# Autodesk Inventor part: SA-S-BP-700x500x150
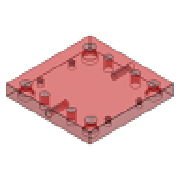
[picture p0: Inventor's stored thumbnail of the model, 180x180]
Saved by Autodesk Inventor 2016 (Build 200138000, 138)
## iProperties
Created: 2015-02
Part Number: SA-S-BP-700x500x150
Material: S 55 C
Description: Core Plate
Document SubType Name: Modeling
Designer: Sandeep
Standard Revision: 1
Manufacturer: FUTABA
Language: en-US
Size Designation: 700x500x150
Categories: <MemberInstance><Categories><Category DisplayName="Mold" InternalName="349578f2-f4d4-4954-8c09-8e99297a61c0" Mnemonic="MOLD"><Category DisplayName="Mold Plates"
Density: 7.85 g/cm^3
Appearance: Dark Red
IsCustomPart: 1
Author: Sandeep
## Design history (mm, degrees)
sketch "Sketch1"
  geometry: L1 (-250, 350)-(250, 350); L2 (250, 350)-(250, -350); L3 (250, -350)-(-250, -350); L4 (-250, -350)-(-250, 350); 7 further points
  constraints: 8 end point, 2 horizontal alignment, 2 midpoint, 2 parallel, 1 horizontal, 1 perpendicular, 1 vertical alignment
  dimensions: "d123" = 500 distance between parallel lines of L2 L4 (= W_); "d124" = 700 distance between parallel lines of L3 L1 (= L); "d125" = 317 vertical distance of point (0, 0) point (-128, 317) (= 0.5 x RP_L); "d126" = 128 horizontal distance of point (0, 0) point (-128, 317) (= 0.5 x RP_W); "d127" = 207 horizontal distance of point (0, 0) point (-207, 307) (= 0.5 x GP_W); "d128" = 307 vertical distance of point (0, 0) point (-207, 307) (= 0.5 x GP_L); "d129" = 205 horizontal distance of point (0, 0) point (-205, 243) (= 0.5 x S1_W); "d130" = 243 vertical distance of point (0, 0) point (-205, 243) (= 0.5 x S1_L); "d140" = 207 horizontal distance of point (207, 307) point (0, 0) (= 0.5 x GP_W)
extrude "Extrusion1" new body sketch "Sketch1" distance "d20" = 150 (= H_); taper "d30" = 0 deg
body "Solid1"
sketch "Sketch2"
  geometry: L1 (500, 0)-(0, 0) reference; 3 further points
  constraints: 1 midpoint, 1 vertical alignment
  dimensions: "d186" = 75 distance from line of L1 point (250, 75) (= 0.5 x H_)
hole "Hole1" sketch "Sketch2" diameter "d104" = 31.67; stored, may be unused: countersink angle "d108" = 90 deg, drill point angle "d110" = 118 deg; dims "d105" = 59 (= le), "d106" = 46 (= GP_d2), "d107" = 10 (= GP_k), "d109" = 82 (= ke)
sketch "Sketch3"
  geometry: L1 (0, 0)-(500, 0) reference; 3 further points
  constraints: 1 midpoint, 1 vertical alignment
  dimensions: "d187" = 75 distance from line of point (250, -75) L1 (= 0.5 x H_)
hole "Hole2" sketch "Sketch3" diameter "d113" = 31.67; stored, may be unused: countersink angle "d117" = 90 deg, drill point angle "d119" = 118 deg; dims "d114" = 59 (= le), "d115" = 46 (= GP_d2), "d116" = 10 (= GP_k), "d118" = 82 (= ke)
hole "Hole3" sketch "Sketch1" diameter "d131" = 13.835; stored, may be unused: countersink angle "d135" = 90 deg, drill point angle "d137" = 118 deg; dims "d132" = 20 (= H_l), "d133" = 4, "d134" = 2, "d136" = 30 (= H_u)
pattern_linear "Rectangular Pattern1" dims "d164" = 243 (computed from S1_L, Ns)
hole "Hole4" sketch "Sketch1" diameter "d141" = 40 (= GP_d1); stored, may be unused: countersink angle "d145" = 90 deg, drill point angle "d147" = 0 deg; dims "d142" = 6, "d143" = 46 (= GP_d2), "d144" = 10 (= GP_k), "d146" = 150 (= H_)
pattern_linear "Rectangular Pattern2" dims "d170" = 614 (computed from GP_L, Nl)
hole "Hole5" sketch "Sketch1" diameter "d148" = 40 (= GP_d1); stored, may be unused: countersink angle "d152" = 90 deg, drill point angle "d154" = 0 deg; dims "d149" = 6, "d150" = 46 (= GP_d2), "d151" = 10 (= GP_k), "d153" = 150 (= H_)
pattern_linear "Rectangular Pattern3" dims "d173" = 612 (computed from GP_L2, GP_L1, Nl)
hole "Hole6" sketch "Sketch1" diameter "d155" = 30 (= RP_dt); stored, may be unused: countersink angle "d159" = 90 deg, drill point angle "d161" = 0 deg; dims "d156" = 6, "d157" = 46 (= GP_d2), "d158" = 10 (= GP_k), "d160" = 150 (= H_)
pattern_linear "Rectangular Pattern4" dims "d176" = 634 (computed from RP_L, Nl), "d179" = 256 (computed from RP_W, Nw)
chamfer "Chamfer1" distance "d180" = 0.5; stored, may be unused: second distance "d181" = 2, angle "d182" = 45 deg
other parameters: "L" = 700 [user parameter; used in 1 equation term], "W_" = 500 [user parameter; used in 3 equation terms], "H_" = 150 [user parameter; used in 8 equation terms], "GP_W" = 414 [user parameter; used in 2 equation terms], "GP_d1" = 40 [user parameter; used in 2 equation terms], "GP_d2" = 46 [user parameter; used in 5 equation terms], "GP_k" = 10 [user parameter; used in 5 equation terms], "S1_L" = 486 [user parameter; used in 2 equation terms], "GP_L1" = 307 [user parameter; used in 1 equation term], "GP_L2" = 305 [user parameter; used in 1 equation term], "RP_L" = 634 [user parameter; used in 2 equation terms], "RP_W" = 256 [user parameter; used in 2 equation terms], "RP_dt" = 30 [user parameter; used in 1 equation term], "GP_L" = 614 [user parameter; used in 2 equation terms], "d102" = 75 (= 0.5 x H_), "d112" = 75 (= 0.5 x H_), "le" = 59 [user parameter; used in 2 equation terms], "ke" = 82 [user parameter; used in 2 equation terms], "H_l" = 20 [user parameter; used in 1 equation term], "H_u" = 30 [user parameter; used in 1 equation term]
